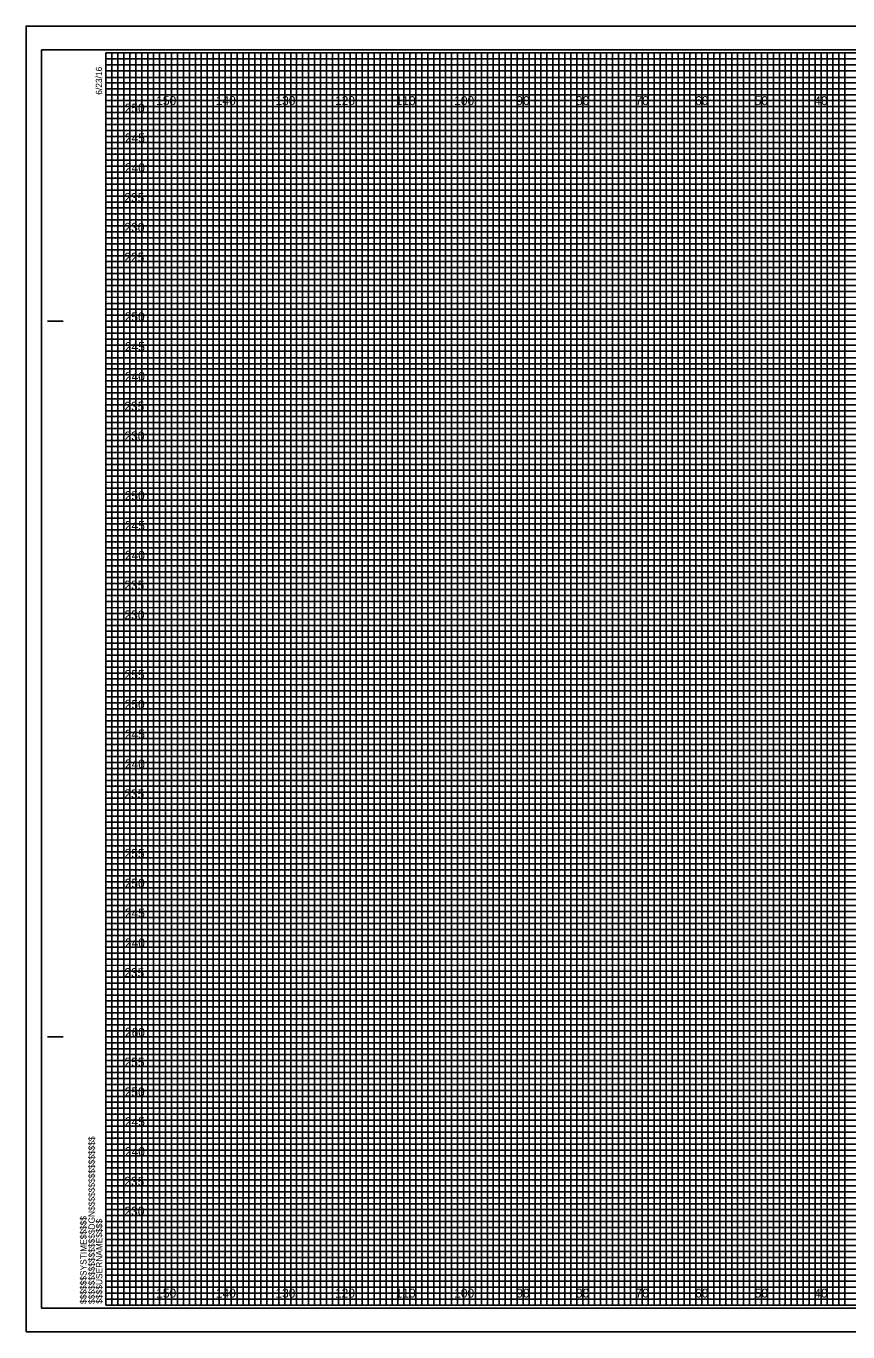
# Model space of a CAD drawing. Extents: x -13 to 323, y -5 to 215.
# Drawn here: x -13.4 to 124.5, y -4.5 to 214.5 of the extents above; entities that cross this region are included whole.
import ezdxf

# ---------------------------------------------------------------- set-up
doc = ezdxf.new("R2010")
doc.units = 0
for name, color, linetype in [('Prop XS Elevation Labels', 7, 'Continuous'), ('Prop XS Offset Labels', 7, 'Continuous'), ('Sheet Cross Section CELL', 7, 'Continuous'), ('Sheet Cross Section Grid Major CELL', 7, 'Continuous'), ('Sheet Cross Section Grid Middle CELL', 7, 'Continuous'), ('Sheet Cross Section Grid Minor 1 CELL', 7, 'Continuous'), ('Sheet Cross Section Grid Minor 2 CELL', 7, 'Continuous'), ('Sheet Cutting Line CELL', 7, 'Continuous'), ('Sheet DOT Grid CELL', 7, 'Continuous'), ('Sheet Plot Border Inside CELL', 7, 'Continuous'), ('Sheet Plot Border Outside CELL', 7, 'Continuous')]:
    doc.layers.add(name, color=color, linetype=linetype)

msp = doc.modelspace()

# ---------------------------------------------------------------- linework, layer by layer
at = {"layer": 'Sheet Cross Section CELL'}
for p, q in [((-9.8, 165), (-7.3, 165)), ((-9.7, 165), (-7.2, 165)), ((-9.8, 45), (-7.3, 45)), ((-9.7, 45), (-7.2, 45)), ((0, 0), (0, 0)), ((0, 0), (0, 0)), ((0, 0), (0, 0)), ((0, 0), (0, 0)), ((0, 0), (0, 0)), ((0, 0), (0, 0)), ((0, 0), (0, 0))]:
    msp.add_line(p, q, dxfattribs=at)
msp.add_lwpolyline([(320, 210), (0, 210), (0, 0), (320, 0)], close=True, dxfattribs=at)
at = {"layer": 'Sheet Cross Section Grid Major CELL'}
for p, q in [((10, 210), (0, 210)), ((10, 0), (10, 210)), ((30, 210), (20, 210)), ((20, 210), (20, 0)), ((30, 0), (30, 210)), ((50, 210), (40, 210)), ((40, 210), (40, 0)), ((50, 0), (50, 210)), ((70, 210), (60, 210)), ((60, 210), (60, 0)), ((70, 0), (70, 210)), ((90, 210), (80, 210)), ((80, 210), (80, 0)), ((90, 0), (90, 210)), ((110, 210), (100, 210)), ((100, 210), (100, 0)), ((110, 0), (110, 210)), ((130, 210), (120, 210)), ((120, 210), (120, 0)), ((20, 0), (10, 0)), ((40, 0), (30, 0)), ((60, 0), (50, 0)), ((80, 0), (70, 0)), ((100, 0), (90, 0)), ((120, 0), (110, 0))]:
    msp.add_line(p, q, dxfattribs=at)
for points in [[(0, 200), (320, 200), (320, 190), (0, 190)], [(0, 180), (320, 180), (320, 170), (0, 170)], [(0, 160), (320, 160), (320, 150), (0, 150)], [(0, 140), (320, 140), (320, 130), (0, 130)], [(0, 120), (320, 120), (320, 110), (0, 110)], [(0, 100), (320, 100), (320, 90), (0, 90)], [(0, 80), (320, 80), (320, 70), (0, 70)], [(0, 60), (320, 60), (320, 50), (0, 50)], [(0, 40), (320, 40), (320, 30), (0, 30)], [(0, 20), (320, 20), (320, 10), (0, 10)]]:
    msp.add_lwpolyline(points, dxfattribs=at)
at = {"layer": 'Sheet Cross Section Grid Middle CELL'}
for points in [[(0, 210), (5, 210), (5, 0), (15, 0), (15, 210), (25, 210), (25, 0), (35, 0), (35, 210), (45, 210), (45, 0), (55, 0), (55, 210), (65, 210), (65, 0), (75, 0), (75, 210), (85, 210), (85, 0), (95, 0), (95, 210), (105, 210), (105, 0), (115, 0), (115, 210), (125, 210)], [(0, 205), (275, 205)], [(0, 185), (320, 185), (320, 195), (0, 195)], [(0, 165), (320, 165), (320, 175), (0, 175)], [(0, 145), (320, 145), (320, 155), (0, 155)], [(0, 125), (320, 125), (320, 135), (0, 135)], [(0, 105), (320, 105), (320, 115), (0, 115)], [(0, 85), (320, 85), (320, 95), (0, 95)], [(0, 65), (320, 65), (320, 75), (0, 75)], [(0, 45), (320, 45), (320, 55), (0, 55)], [(0, 25), (320, 25), (320, 35), (0, 35)], [(0, 5), (320, 5), (320, 15), (0, 15)]]:
    msp.add_lwpolyline(points, dxfattribs=at)
at = {"layer": 'Sheet Cross Section Grid Minor 1 CELL'}
for p, q in [((0, 209), (260, 209)), ((260, 207.98), (0, 207.98)), ((0, 207.98), (0, 207)), ((0, 207), (260, 207)), ((260, 205.89), (0, 205.89)), ((0, 205.89), (0, 204)), ((0, 204), (320, 204))]:
    msp.add_line(p, q, dxfattribs=at)
for points in [[(0, 203), (270, 203), (320, 203), (320, 202), (0, 202)], [(0, 201), (320, 201), (320, 199), (0, 199)], [(0, 198), (320, 198), (320, 197), (0, 196.98)], [(0, 196), (320, 196), (320, 194), (0, 194)], [(0, 193), (320, 193), (320, 192), (0, 192)], [(0, 191), (320, 191), (320, 189), (0, 189)], [(0, 188), (320, 188), (320, 187), (0, 187)], [(0, 186), (320, 186), (320, 184), (0, 184)], [(0, 183), (320, 183), (320, 182), (0, 182)], [(0, 181), (320, 181), (320, 179), (0, 179)], [(0, 178), (320, 178), (320, 177), (0, 177)], [(0, 176), (320, 176), (320, 173.95), (320, 173), (320, 172), (0, 172)], [(0, 174), (320, 174), (320, 173), (0, 173)], [(0, 171), (320, 171), (320, 169), (0, 169.03)], [(0, 169.03), (320, 169), (320, 168), (0, 168)], [(0, 167), (320, 167), (320, 166), (0, 166)], [(0, 164), (320, 164), (320, 163), (0, 163)], [(0, 162), (320, 162), (320, 161), (0, 161)], [(-0.07, 158.89), (320, 158.89), (320, 157.88), (-0.07, 157.88)], [(0, 157), (320, 157), (320, 156), (0, 156)], [(0, 154), (320, 154), (320, 153), (0, 153)], [(0, 152), (320, 152), (320, 151), (0, 151)], [(0, 149), (320, 149), (320, 148), (0, 148)], [(0, 147), (320, 147), (320, 146), (0, 146)], [(0, 144), (320, 144), (320, 143), (0, 143)], [(0, 142), (320, 142), (320, 141), (0, 141)], [(0, 139), (320, 139), (319.99, 137.98), (0, 138)], [(0, 137), (320, 137), (320, 136), (0, 136)], [(0, 134), (320, 134), (320, 133), (0, 133)], [(0, 132), (320, 132), (320, 131), (0, 131)], [(0, 129), (320, 129), (320, 128), (0, 128)], [(0, 127), (320, 127), (320, 126), (0, 126)], [(0, 124), (320, 124), (320, 123), (0, 123)], [(0, 122), (320, 122), (320, 121), (0, 121)], [(0, 119), (320, 119), (320, 118), (0, 118)], [(0, 116.99), (320.07, 116.91), (320, 116), (0, 116)], [(0, 114), (320, 114), (320, 113), (0, 113)], [(0, 112), (320, 112), (320, 111), (0, 111)], [(0, 109), (320, 109), (320, 108), (0, 108)], [(0, 107), (320, 107), (320, 106), (0, 106)], [(0, 104), (320, 104), (320, 103), (0, 103)], [(0, 102), (320, 102), (320, 101), (0, 101)], [(0, 99), (320, 99), (320, 98), (0, 98)], [(0, 97), (320, 97), (320, 96), (0, 96)], [(0, 94), (320, 94), (320, 93), (0, 93)], [(0, 92), (320, 92), (320, 91), (0, 91)], [(0, 89), (320, 89), (320, 88), (0, 88)], [(0, 87), (320, 87), (320, 86), (0, 86)], [(0, 84), (320, 84), (320, 83), (0, 83)], [(0, 82), (320, 82), (320, 81), (0, 81)], [(0, 79), (320, 79), (319.99, 77.98), (0, 78)], [(0, 77), (320, 77), (320, 76), (0, 76)], [(0, 74), (320, 74), (320, 73), (0, 73)], [(0, 72), (320, 72), (320, 71), (0, 71)], [(0, 69), (320, 69), (320, 68), (0, 68)], [(0, 67), (320, 67), (320, 66), (0, 66)], [(0, 64), (320, 64), (320, 63), (0, 63)], [(0, 62), (320, 62), (320, 61), (0, 61)], [(0, 59), (320, 59), (320, 58), (0, 58)], [(0, 56.99), (320.07, 56.91), (320, 56), (0, 56)], [(0, 54), (320, 54), (320, 53), (0, 53)], [(0, 52), (320, 52), (320, 51), (0, 51)], [(0, 49), (320, 49), (320, 48), (0, 48)], [(0, 47), (320, 47), (320, 46), (0, 46)], [(0, 44), (320, 44), (320, 43), (0, 43)], [(0, 42), (320, 42), (320, 41), (0, 41)], [(0, 39), (320, 39), (320, 38), (0, 38)], [(0, 37), (320, 37), (320, 36), (0, 36)], [(0, 34), (320, 34), (320, 33), (0, 33)], [(0, 32), (320, 32), (320, 31), (0, 31)], [(0, 29), (320, 29), (320, 28), (0, 28)], [(0, 27), (320, 27), (320, 26), (0, 26)], [(0, 24), (320, 24), (320, 23), (0, 23)], [(0, 22), (320, 22), (320, 21), (0, 21)], [(0, 19), (320, 19), (320, 18), (0, 18)], [(0, 17), (320, 17), (320, 16), (0, 16)], [(0, 14), (320, 14), (320, 13), (0, 13)], [(0, 12), (320, 12), (320, 11), (0, 11)], [(0, 9), (320, 9), (320, 8), (0, 8)], [(0, 7), (320, 7), (320, 6), (0, 6)], [(0, 4), (320, 4), (320, 3), (0, 3)], [(0, 2), (320, 2), (320, 1), (0, 1)]]:
    msp.add_lwpolyline(points, dxfattribs=at)
at = {"layer": 'Sheet Cross Section Grid Minor 2 CELL'}
for points in [[(0, 0), (1, 0), (1, 210), (2, 210), (2, 0)], [(2, 0), (3, 0), (3, 210), (4, 210), (4, 0)], [(5, 0), (6, 0), (6, 210), (7, 210), (7, 0)], [(7, 0), (8, 0), (8, 210), (9, 210), (9, 0)], [(10, 0), (11, 0), (11, 210), (12, 210), (12, 0)], [(12, 0), (13, 0), (13, 210), (14, 210), (14, 0)], [(15, 0), (16, 0), (16, 210), (17, 210), (17, 0)], [(17, 0), (18, 0), (18, 210), (19, 210), (19, 0)], [(20, 0), (21, 0), (21, 210), (22, 210), (22, 0)], [(22, 0), (23, 0), (23, 210), (24, 210), (24, 0)], [(25, 0), (26, 0), (26, 210), (27, 210), (27, 0)], [(27, 0), (28, 0), (28, 210), (29, 210), (29, 0)], [(30, 0), (31, 0), (31, 210), (32, 210), (32, 0)], [(32, 0), (33, 0), (33, 210), (34, 210), (34, 0)], [(35, 0), (36, 0), (36, 210), (37, 210), (37, 0)], [(37, 0), (38, 0), (38, 210), (39, 210), (39, 0)], [(40, 0), (41, 0), (41, 210), (42, 210), (42, 0)], [(42, 0), (43, 0), (43, 210), (44, 210), (44, 0)], [(45, 0), (46, 0), (46, 210), (47, 210), (47, 0)], [(47, 0), (48, 0), (48, 210), (49, 210), (49, 0)], [(50, 0), (51, 0), (51, 210), (52, 210), (52, 0)], [(52, 0), (53, 0), (53, 210), (54, 210), (54, 0)], [(55, 0), (56, 0), (56, 210), (57, 210), (57, 0)], [(57, 0), (58, 0), (58, 210), (59, 210), (59, 0)], [(60, 0), (61, 0), (61, 210), (62, 210), (62, 0)], [(62, 0), (63, 0), (63, 210), (64, 210), (64, 0)], [(65, 0), (66, 0), (66, 210), (67, 210), (67, 0)], [(67, 0), (68, 0), (68, 210), (69, 210), (69, 0)], [(70, 0), (71, 0), (71, 210), (72, 210), (72, 0)], [(72, 0), (73, 0), (73, 210), (74, 210), (74, 0)], [(75, 0), (76, 0), (76, 210), (77, 210), (77, 0)], [(77, 0), (78, 0), (78, 210), (79, 210), (79, 0)], [(80, 0), (81, 0), (81, 210), (82, 210), (82, 0)], [(82, 0), (83, 0), (83, 210), (84, 210), (84, 0)], [(85, 0), (86, 0), (86, 210), (87, 210), (87, 0)], [(87, 0), (88, 0), (88, 210), (89, 210), (89, 0)], [(90, 0), (91, 0), (91, 210), (92, 210), (92, 0)], [(92, 0), (93, 0), (93, 210), (94, 210), (94, 0)], [(95, 0), (96, 0), (96, 210), (97, 210), (97, 0)], [(97, 0), (98, 0), (98, 210), (99, 210), (99, 0)], [(100, 0), (101, 0), (101, 210), (102, 210), (102, 0)], [(102, 0), (103, 0), (103, 210), (104, 210), (104, 0)], [(105, 0), (106, 0), (106, 210), (107, 210), (107, 0)], [(107, 0), (108, 0), (108, 210), (109, 210), (109, 0)], [(110, 0), (111, 0), (111, 210), (112, 210), (112, 0)], [(112, 0), (113, 0), (113, 210), (114, 210), (114, 0)], [(115, 0), (116, 0), (116, 210), (117, 210), (117, 0)], [(117, 0), (118, 0), (118, 210), (119, 210), (119, 0)], [(120, 0), (121, 0), (121, 210), (122, 210), (122, 0)], [(122, 0), (123, 0), (123, 210), (124, 210), (124, 0)]]:
    msp.add_lwpolyline(points, dxfattribs=at)
at = {"layer": 'Sheet Cutting Line CELL'}
for p, q in [((323.3, 214.5), (-13.4, 214.5)), ((-13.4, 214.5), (-13.4, -4.5)), ((-13.4, -4.5), (323.3, -4.5))]:
    msp.add_line(p, q, dxfattribs=at)
at = {"layer": 'Sheet DOT Grid CELL'}
for p, q in [((10, 0), (10, 210)), ((20, 0), (20, 210)), ((30, 0), (30, 210)), ((40, 0), (40, 210)), ((50, 0), (50, 210)), ((60, 0), (60, 210)), ((70, 0), (70, 210)), ((80, 0), (80, 210)), ((90, 0), (90, 210)), ((100, 0), (100, 210)), ((110, 0), (110, 210)), ((120, 0), (120, 210)), ((0, 200), (320, 200)), ((0, 190), (320, 190)), ((0, 180), (320, 180)), ((0, 170), (320, 170)), ((0, 160), (320, 160)), ((0, 150), (320, 150)), ((0, 140), (320, 140)), ((0, 130), (320, 130)), ((0, 120), (320, 120)), ((0, 110), (320, 110)), ((0, 100), (320, 100)), ((0, 90), (320, 90)), ((0, 80), (320, 80)), ((0, 70), (320, 70)), ((0, 60), (320, 60)), ((0, 50), (320, 50)), ((0, 40), (320, 40)), ((0, 30), (320, 30)), ((0, 20), (320, 20)), ((0, 10), (320, 10))]:
    msp.add_line(p, q, dxfattribs=at)
at = {"layer": 'Sheet Plot Border Inside CELL'}
msp.add_lwpolyline([(-10.8, -0.5), (322.4, -0.5), (322.4, 210.5), (-10.8, 210.5)], close=True, dxfattribs=at)
at = {"layer": 'Sheet Plot Border Outside CELL'}
msp.add_lwpolyline([(-13.4, -4.5), (323.3, -4.5), (323.3, 214.5), (-13.4, 214.5)], close=True, dxfattribs=at)

# ---------------------------------------------------------------- texts
at = {"layer": 'Prop XS Elevation Labels'}
for s, p in [('250', (3.15, 200)), ('245', (3.18, 195)), ('240', (3.19, 190)), ('235', (3.09, 185)), ('230', (3.11, 180)), ('225', (3.1, 175)), ('250', (3.15, 165)), ('245', (3.18, 160)), ('240', (3.19, 155)), ('235', (3.09, 150)), ('230', (3.11, 145)), ('250', (3.15, 135)), ('245', (3.18, 130)), ('240', (3.19, 125)), ('235', (3.09, 120)), ('230', (3.11, 115)), ('255', (3.13, 105)), ('250', (3.15, 100)), ('245', (3.18, 95)), ('240', (3.19, 90)), ('235', (3.09, 85)), ('255', (3.13, 75)), ('250', (3.15, 70)), ('245', (3.18, 65)), ('240', (3.19, 60)), ('235', (3.09, 55)), ('260', (3.19, 45)), ('255', (3.13, 40)), ('250', (3.15, 35)), ('245', (3.18, 30)), ('240', (3.19, 25)), ('235', (3.09, 20)), ('230', (3.11, 15))]:
    msp.add_text(s, height=1.5, dxfattribs=at).set_placement(p)
at = {"layer": 'Prop XS Offset Labels'}
for s, p in [('150', (8.44, 201.25)), ('140', (18.44, 201.25)), ('130', (28.44, 201.25)), ('120', (38.44, 201.25)), ('110', (48.62, 201.25)), ('100', (58.44, 201.25)), ('90', (68.86, 201.25)), ('80', (78.86, 201.25)), ('70', (88.86, 201.25)), ('60', (98.86, 201.25)), ('50', (108.86, 201.25)), ('40', (118.86, 201.25)), ('150', (8.44, 1.25)), ('140', (18.44, 1.25)), ('130', (28.44, 1.25)), ('120', (38.44, 1.25)), ('110', (48.62, 1.25)), ('100', (58.44, 1.25)), ('90', (68.86, 1.25)), ('80', (78.86, 1.25)), ('70', (88.86, 1.25)), ('60', (98.86, 1.25)), ('50', (108.86, 1.25)), ('40', (118.86, 1.25))]:
    msp.add_text(s, height=1.5, dxfattribs=at).set_placement(p)
at = {"layer": 'Sheet Cross Section CELL'}
for s, p in [('6/23/16', (-0.65, 203)), ('$$$$$$$$$$$$$$$$DGN$$$$$$$$$$$$$$$$', (-1.88, 0.18)), ('$$$$$$SYSTIME$$$$$', (-3.26, 0.18)), ('$$$$USERNAME$$$$', (-0.62, 0.23))]:
    msp.add_text(s, height=1.05, rotation=90, dxfattribs=at).set_placement(p)

doc.saveas('drawing.dxf')
